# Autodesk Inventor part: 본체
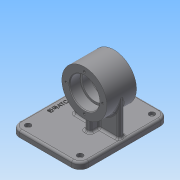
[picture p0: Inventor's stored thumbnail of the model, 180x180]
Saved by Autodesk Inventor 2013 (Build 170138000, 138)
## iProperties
Created: 2019-09
Part Number: 본체
Material: 일반
Document SubType Name: Modeling
Designer: Administrator
Density: 1 g/cm^3
Author: Administrator
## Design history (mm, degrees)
sketch "스케치1"
  geometry: L1 (-62, -59)-(36, -59); L2 (36, -59)-(36, -50); L3 (36, -50)-(-62, -50); L4 (-62, -50)-(-62, -59); L5 (-62, -59)-(36, -50); L6 (36, -59)-(-62, -50); C1 r 32 at (0, 0); 2 further points
  constraints: 12 end point, 2 midpoint, 2 parallel, 1 centre point, 1 coincident, 1 horizontal, 1 perpendicular
  dimensions: "d0" = 64 diameter of C1; "d1" = 98 distance of L3.end L2.end; "d2" = 9 distance of L2.end L1.end; "d3" = 59 distance from line of C1.centre L1; "d4" = 36 distance from line of point (0, 0) L2
extrude "돌출1" new body sketch "스케치1" distance "d5" = 21; taper "d6" = 0 deg
sketch "스케치2"
  geometry: C1 r 32 at (0, 0) reference
hole "구멍1" sketch "스케치2" at (0, 0) diameter "d9" = 36; stored, may be unused: countersink angle "d13" = 90 deg, drill point angle "d15" = 118 deg; dims "d10" = 6, "d11" = 42, "d12" = 15, "d14" = 8
sketch "스케치3"
  geometry: C1 r 21 at (0, 0) reference; 1 further point
  constraints: 1 vertical alignment
  dimensions: "d16" = 26 distance of C1.centre point (0, 26)
hole "구멍2" sketch "스케치3" at (0, 26) diameter "d17" = 3.242; stored, may be unused: countersink angle "d21" = 90 deg, drill point angle "d23" = 118 deg; dims "d18" = 8, "d19" = 42, "d20" = 15, "d22" = 10
chamfer "모따기1" distance "d27" = 1; stored, may be unused: second distance "d28" = 2, angle "d29" = 45 deg
fillet "모깎기1" dims "d30" = 0.3
extrude "돌출3" join sketch "스케치1" stored distance "d31" = 126; taper "d32" = 0 deg
sketch "스케치4"
  geometry: L1 (66, 46)-(58, 46); L2 (58, 46)-(58, 80); L3 (58, 80)-(66, 80); L4 (66, 80)-(66, 46); L5 (66, 46)-(58, 80); L6 (58, 46)-(66, 80); L7 (30, 59)-(94, 59); L8 (94, 59)-(94, 67); L9 (94, 67)-(30, 67); L10 (30, 67)-(30, 59); L11 (30, 59)-(94, 67); L12 (94, 59)-(30, 67); 5 further points
  constraints: 24 end point, 7 midpoint, 4 parallel, 2 horizontal, 2 perpendicular, 1 coincident
  dimensions: "d33" = 8 distance of L2.end L3.end; "d34" = 34 distance of L1.end L2.end; "d35" = 64 distance of L9.end L8.end; "d36" = 8 distance of L8.end L7.end
extrude "돌출4" join sketch "스케치4" stored distance "d37" = 126; taper "d38" = 0 deg
extrude "돌출5" join sketch "스케치4" stored distance "d39" = 126; taper "d40" = 0 deg
sketch "스케치5"
  geometry: C1 r 18 at (0, 0) reference; C2 r 18 at (0, 0)
  constraints: 1 centre point, 1 coincident
  dimensions: "d41" = 36 diameter of C2
extrude "돌출6" cut sketch "스케치5" distance "d42" = 126; taper "d43" = 0 deg
sketch "스케치6"
  geometry: 1 further point
fillet "모깎기2" dims "d44" = 12
sketch "스케치7"
  geometry: A1 r 12 centre (74, 12) between (74, 0) and (86, 12) reference; 1 further point
hole "구멍3" sketch "스케치7" at (74, 12) diameter "d45" = 4.5; stored, may be unused: countersink angle "d49" = 90 deg, drill point angle "d51" = 118 deg; dims "d46" = 8, "d47" = 8, "d48" = 4.4, "d50" = 10
node "작업 평면1"
fillet "모깎기3" dims "d52" = 3
fillet "모깎기4" dims "d53" = 3
fillet "모깎기5" dims "d54" = 3
sketch "스케치8"
  geometry: L1 (74, 3)-(0, 3) reference; L2 (-12, -111)-(-12, -9) reference; 2 further points
  constraints: 1 other
  dimensions: "d55" = 63 distance from line of L1 point (-2, -60); "d56" = 10 distance from line of L2 point (-2, -60)
feature "엠보싱1" sketch "스케치8" dims "d57" = 0.5, "d58" = 0
fillet "모깎기6" dims "d59" = 3
fillet "모깎기7" dims "d60" = 3
node "솔리드1"
pattern_circular "원형 패턴1" dims angle "d25" = 360 deg
mirror "대칭1"
mirror "대칭2"
mirror "대칭3"
